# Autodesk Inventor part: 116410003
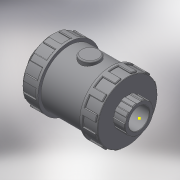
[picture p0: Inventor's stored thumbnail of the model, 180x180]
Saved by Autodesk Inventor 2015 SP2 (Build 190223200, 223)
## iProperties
Created: 2017-11
Part Number: 116410003
Material: Generic
Description: PLASSON FOOT VALVE THR PVC 3/8"
Document SubType Name: Modeling
Designer: KIM
Density: 1 g/cm^3
Appearance: Default
Author: KIM
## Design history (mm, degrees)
derived "116410 - 116010.ipt"
feature "Solid1::116410 - 116010.ipt"
tag "TaggingFeature1"
body "Solid1"
other parameters: "d0" = 71, "d1" = 14.95, "d2" = 45, "d3" = 12, "d4" = 11.96, "d5" = 8.4, "d7" = 20.93, "d8" = 40.5, "d13" = 0.4485, "d23" = 12, "d24" = 43.2, "d25" = 0.299, "d26" = 0.4485, "d27" = 6.75, "d28" = 3.375, "d29" = 9, "d30" = 0, "d35" = 0.4485, "d39" = 22.5, "d45" = 360 deg, "d47" = 0.299, "d50" = 22.5, "d51" = 13.5, "d53" = 0, "d54" = 0.9, "d55" = 2.99, "d56" = 1.495, "d58" = 0, "d59" = 0.4485, "d61" = 360 deg, "G_" = 14.95, "l_" = 12, "H_" = 71, "K_" = 45
